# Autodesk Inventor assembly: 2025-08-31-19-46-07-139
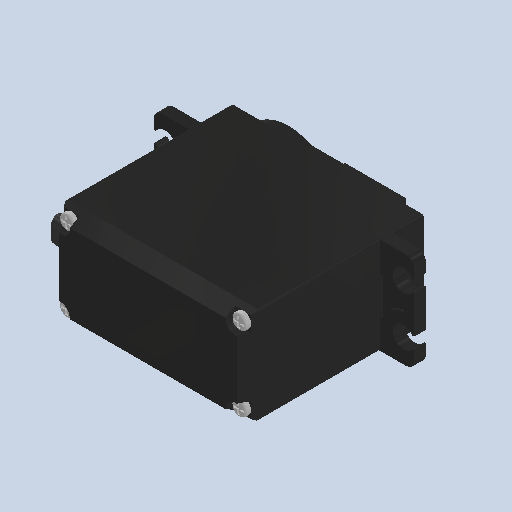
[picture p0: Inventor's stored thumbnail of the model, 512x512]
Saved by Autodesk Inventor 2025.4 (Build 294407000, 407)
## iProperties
Created: 2026-09
Part Number: 2025-08-31-19-46-07-139
Document SubType Name: Assembly
Designer: AdminForWorker
Title: Servo
Author: AdminForWorker
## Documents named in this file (5)
- c:\worker\convert-fusion-r05-cosv3\tmp\job-1\19\temp\files\ca3d996b-dda0-445d-8bee-12a194174ca8\Servo_1.iam
- c:\worker\convert-fusion-r05-cosv3\tmp\job-1\19\temp\files\ca3d996b-dda0-445d-8bee-12a194174ca8\com_top_1.iam
- c:\worker\convert-fusion-r05-cosv3\tmp\job-1\19\temp\files\ca3d996b-dda0-445d-8bee-12a194174ca8\com_but.ipt
- c:\worker\convert-fusion-r05-cosv3\tmp\job-1\19\temp\files\ca3d996b-dda0-445d-8bee-12a194174ca8\Gear.ipt
- c:\worker\convert-fusion-r05-cosv3\tmp\job-1\19\temp\files\ca3d996b-dda0-445d-8bee-12a194174ca8\bolts.ipt
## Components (4 placed, 4 different names)
1. com_top:1 [sub-assembly]
2. com_but:1
3. Gear:1
4. bolts:1
